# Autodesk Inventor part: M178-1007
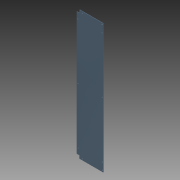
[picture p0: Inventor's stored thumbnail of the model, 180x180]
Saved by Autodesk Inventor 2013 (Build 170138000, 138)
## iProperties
Created: 2004-11
Part Number: M178-1007
Material: Allgemein
Document SubType Name: Modeling
Designer: Autodesk, Inc.
Manufacturer: Standard
Standards Organization: Custom
Description: WORKSTATION, LOWER SHELF
Mass: 4394.89 g
Surface Area: 14146.2 cm^2
Volume: 4394.89 cm^3
Density: 1 g/cm^3
CAGE: 1LJX3
Dept. ID: Product Design
Description #2: ---
Finish #1: ---
Finish #2: ---
Material ID: ---
Project Number: ---
Author: Autodesk, Inc.
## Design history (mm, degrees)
sketch "Sketch1"
  geometry: L1 (-190.5, -914.4)-(190.5, -914.4); L2 (190.5, -914.4)-(190.5, 914.4); L3 (190.5, 914.4)-(-190.5, 914.4); L4 (-190.5, 914.4)-(-190.5, -914.4); L5 (-190.5, -914.4)-(-148.5, -914.4); L6 (-148.5, -914.4)-(-148.5, -872.4); L7 (-148.5, -872.4)-(-190.5, -872.4); L8 (-190.5, -872.4)-(-190.5, -914.4); L9 (-190.5, 914.4)-(-148.5, 914.4); L10 (-148.5, 914.4)-(-148.5, 872.4); L11 (-148.5, 872.4)-(-190.5, 872.4); L12 (-190.5, 872.4)-(-190.5, 914.4); 3 further points
  constraints: 24 end point, 6 parallel, 3 equal length, 3 horizontal, 3 perpendicular, 2 midpoint, 1 horizontal alignment, 1 vertical alignment
  dimensions: "d0" = 1828.8 distance of L1.end L2.end; "d1" = 381 distance of L1.start L1.end; "d2" = 42 distance of L6.end L7.end
extrude "Extrusion1" new body sketch "Sketch1" distance "d3" = 6.35; taper "d4" = 0 deg
sketch "Sketch2"
  geometry: L1 (190.5, -914.4)-(-148.5, -914.4) reference; L2 (190.5, 914.4)-(190.5, -914.4) reference; 2 further points
  constraints: 1 vertical alignment
  dimensions: "d5" = 20 distance from line of point (170.5, -894.4) L1; "d6" = 20 distance from line of point (170.5, -894.4) L2; "d7" = 120 distance from line of point (170.5, -794.4) L1
hole "Hole1" sketch "Sketch2" diameter "d8" = 8.9916; stored, may be unused: countersink angle "d12" = 90 deg, drill point angle "d14" = 118 deg; dims "d9" = 12.7, "d10" = 17.2974, "d11" = 6.35, "d13" = 19.05
hole "Hole2" sketch "Sketch2" diameter "d15" = 8.9916; stored, may be unused: countersink angle "d19" = 90 deg, drill point angle "d21" = 118 deg; dims "d16" = 12.7, "d17" = 17.2974, "d18" = 6.35, "d20" = 19.05
pattern_linear "Rectangular Pattern1" dims "d24" = 281 (computed from d1), "d27" = 1788.8 (computed from d0)
pattern_linear "Rectangular Pattern2" dims "d30" = 1588.8 (= d0 - 2 x d7), "d33" = 341 (computed from d1)
body "Solid1"
